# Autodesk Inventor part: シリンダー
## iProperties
Created: 2008-02
Part Number: シリンダー
Document SubType Name: Modeling
Designer: t-ikumi
Density: 1 g/cm^3
Author: t-ikumi
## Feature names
1. 押し出し1 [Extrusion]
2. 押し出し4 [Extrusion]
3. シェル1
4. 押し出し8 [Extrusion]
5. 押し出し9 [Extrusion]
